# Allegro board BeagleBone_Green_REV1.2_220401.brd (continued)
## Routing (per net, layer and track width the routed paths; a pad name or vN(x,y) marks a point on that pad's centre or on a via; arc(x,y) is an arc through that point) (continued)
UART0_RX: length 28.4
  TOP w0.121: v1(40.92,25.21) U5.E15
  LYR4 w0.133: v1(43.61,11.33) 41.4,13.54 41.4,14.66 40.69,15.37 40.69,20.47 39.45,21.71 39.45,24.28 39.96,24.79 40.5,24.79 v1(40.92,25.21)
  BOTTOM w0.121: U15.6 53.22,11.68 52.33,12.57 50.16,12.57 49.31,11.72 44.01,11.72 v1(43.61,11.33)
UART0_TX: length 28.7
  TOP w0.121: v1(40.12,25.21) U5.E16
  LYR4 w0.133: v1(40.12,25.21) 40.01,25.21 39.19,24.39 39.19,21.59 40.41,20.37 40.41,15.01 41.17,14.26 41.17,13.14 v1(43.03,11.28)
  BOTTOM w0.121: U15.5 53.23,12.18 52.59,12.81 49.9,12.81 49.12,12.04 43.41,12.04 43.03,11.66 v1(43.03,11.28)
UART1_RXD: length 25.6
  TOP w0.121: v1(40.13,24.38) 40.13,24.42 U5.D16
  LYR4 w0.121: v1(40.13,24.38) 40.52,24 40.52,21.84 40.72,21.64
  LYR4 w0.133: 40.72,21.64 41.5,20.85 41.5,15.62 42.21,14.91 42.21,14.04 44.58,11.68 44.58,9.4 v1(45.09,8.89)
  BOTTOM w0.121: P9.26 48.77,5.84 47.75,5.84 46.35,7.24 46.35,8.13 45.59,8.89 v1(45.09,8.89)
UART1_TXD: length 23.3
  TOP w0.121: v1(40.92,24.41) U5.D15
  LYR4 w0.121: 41.32,23.37 41.32,24.01 v1(40.92,24.41)
  LYR4 w0.133: P9.24 46.13,5.94 46.13,8.74 44.88,9.98 44.88,11.71 42.52,14.07 42.52,15.01 41.74,15.79 41.74,21 41.33,21.41 41.33,23.35 41.32,23.37
UART2_RXD: length 83.2
  TOP w0.121: J5.1 v1(78.23,36.4) ; U5.A17 39.72,22.19 38.09,20.57 38.09,12.99 40.74,10.34 v1(40.74,10.21) 40.84,10.11 40.84,6.78 41.66,5.97 43.56,5.97 P9.22
  LYR3 w0.133: v1(40.74,10.21) 41.01,10.48 46.16,10.48 46.93,9.71 54.79,9.71 54.94,9.85 54.94,10.36 55.37,10.79 56.9,10.79 57.94,11.84 69.24,11.84 78.69,21.28 78.69,35.94 v1(78.23,36.4)
UART2_TXD: length 84.2
  TOP w0.121: U5.B17 39.32,22.81 39.32,22.17 37.85,20.7 37.85,12.45 v1(40.03,10.26) 40.51,9.78 40.51,6.6 41.53,5.59 43.05,5.59 43.81,4.83 43.81,3.17 P9.21 ; J5.2 v1(78.23,34.4)
  LYR3 w0.133: v1(78.23,34.4) 78.23,21.46 68.97,12.2 55.89,12.2 53.63,9.94 47.08,9.94 46.3,10.72 40.49,10.72 v1(40.03,10.26)
UART4_RXD: length 41.6
  TOP w0.121: v1(37.08,36.7) 37.21,36.58 37.21,36.35 37.52,36.04 37.52,36 38.7,34.81 39.32,34.81 U5.T17
  LYR4 w0.133: v1(33.15,6.48) 33.15,16.38 34.29,17.53 34.29,21.69 34.51,21.9 34.51,21.93 34.54,21.97 34.54,35.31 35.37,36.13 36.46,36.13 37.03,36.7 v1(37.08,36.7)
  BOTTOM w0.121: P9.11 33.66,3.17 33.66,5.4 33.15,5.91 v1(33.15,6.48)
UART4_TXD: length 44.6
  TOP w0.121: U5.U17 39.32,35.61 38.68,35.61 38.35,35.94 38.35,36.06 38.2,36.21 v1(38.2,36.22) ; P9.13 33.66,3.17 33.66,5.08 v1(32.26,6.48)
  LYR4 w0.121: 38.19,36.22 v1(38.2,36.22)
  LYR4 w0.133: 38.19,36.22 37.92,36.22 37.49,36.65 37.49,37.69 37.08,38.1 35.81,38.1 34.04,36.32 34.04,22.1 33.78,21.84 33.78,18.03 32.26,16.51 v1(32.26,6.48)
USB0_DM: length 42.5
  TOP w0.114: v1(10.79,43.26) 10.79,43.27 10.79,43.56 10.92,43.69 11.34,43.69 11.66,43.37 11.66,42.49 12.24,41.91 U10.2 12.8,41.91 13.02,42.13 13.02,42.69 13.13,42.8 15.49,42.8 16.48,41.81 16.48,41.29 17.38,40.39 22.21,40.39 25.74,36.86 29.42,36.86 30.08,36.2 33.87,36.2 34.52,35.55 34.52,35.28 34.69,35.11 34.96,35.11 35.18,34.89 35.18,34.67 35.36,34.49 35.57,34.49 36.07,34 36.07,32.94 36.78,32.23 37.03,32.23 37.18,32.38 37.45,32.38 37.59,32.23 37.92,32.23 38.07,32.38 38.4,32.38 38.65,32.13 38.8,32.13 U5.N18
  BOTTOM w0.114: P4.2 10.58,43.48 v1(10.79,43.26)
USB0_DP: length 42.5
  TOP w0.114: v1(10.79,44.07) 10.9,43.97 11.46,43.97 11.94,43.49 11.94,42.61 12.14,42.41 U10.1 12.7,42.53 12.7,42.88 12.9,43.08 15.61,43.08 16.76,41.92 16.76,41.4 17.5,40.67 22.33,40.67 25.86,37.13 29.54,37.13 30.2,36.47 33.99,36.47 36.35,34.11 36.35,33.06 36.75,32.66 38.51,32.66 38.76,32.41 39.32,32.41 U5.N17
  BOTTOM w0.114: v1(10.79,44.07) 10.79,44.02 10.54,43.76 5.9,43.76 5.52,44.13 P4.3
USB0_ID: length 48.4
  TOP w0.121: U5.P16 v1(40.12,33.21) ; U10.3 12.58,41.02 12.71,40.89 14.61,40.89 v1(15.62,41.91)
  LYR3 w0.133: v1(15.62,41.91) 16.01,41.91 16.09,41.83 26.47,41.83 27.05,41.25 31.19,41.25 31.21,41.22 31.88,41.22 32.52,40.58 34.73,40.58 35.61,39.7 36.5,39.7 37.49,38.71 37.49,36.3 38.52,35.26 40.25,35.26 40.49,35.03 40.49,33.58 v1(40.12,33.21)
  BOTTOM w0.121: v1(15.62,41.91) 15.54,41.99 15.54,42.98 13.56,44.96 5.85,44.96 5.68,44.78 P4.4
USB1_DM: length 61.1
  TOP w0.114: v1(36.22,34.98) 36.14,34.9 36.14,34.74 36.33,34.54 37.17,34.54 37.98,33.73 38.8,33.73 U5.R18
  LYR3 w0.127: v1(15.06,16.36) 15.06,16.28 14.78,16 14.42,16 14,16.43 14,18.19 16.99,21.18 18.26,21.18 21.26,24.18 21.26,27.1 22.23,28.07 22.23,34.29 21.84,34.67 20.62,34.67 19.68,35.61 19.68,38.56 19.99,38.86 22.61,38.86 23.62,37.85 33.91,37.85 35.97,35.79 35.97,35.38 36.22,35.13 v1(36.22,34.98)
  BOTTOM w0.114: P3.2 10.28,12.17 10.92,11.53 12.2,11.53 13.94,13.26 13.94,13.54 13.72,13.76 U9.2 13.72,14.45 13.87,14.61 14.51,14.61 14.68,14.77 14.68,16.08 14.96,16.36 v1(15.06,16.36)
USB1_DP: length 61.1
  TOP w0.114: U5.R17 39.64,33.61 39.24,34.01 38.1,34.01 37.13,34.98 v1(36.86,34.98)
  LYR3 w0.127: v1(36.86,34.98) 36.73,35.1 36.68,35.1 36.53,35.25 36.27,35.51 36.27,35.92 34.04,38.15 23.75,38.15 22.73,39.17 19.86,39.17 19.38,38.68 19.38,35.48 20.5,34.37 21.72,34.37 21.92,34.16 21.92,28.19 20.95,27.23 20.95,24.31 18.14,21.49 16.87,21.49 13.69,18.31 13.69,16.3 14.24,15.75 v1(15.14,15.75)
  BOTTOM w0.114: P3.3 10.72,11.25 12.32,11.25 14.22,13.15 U9.1 14.22,14.24 14.3,14.33 14.63,14.33 14.96,14.66 14.96,15.57 v1(15.14,15.75)
USB1_DRVVBUS: length 60.9
  TOP w0.121: U5.F15 v1(40.92,26.01)
  LYR3 w0.133: v1(3.62,7.59) 3.62,8.33 4.58,9.3 21.69,9.3 22.23,8.76 28.88,8.76 29.48,8.17 36.24,8.17 36.29,8.22 39.66,8.22 v1(39.85,8.41)
  LYR4 w0.121: 38.93,24.76 40.18,26.01 v1(40.92,26.01)
  LYR4 w0.133: 38.93,24.76 38.93,21.32 39.52,20.73 39.52,19.41 40.13,18.8 40.13,14.71 40.59,14.25 40.59,12.4 39.5,11.3 39.5,8.76 v1(39.85,8.41)
  BOTTOM w0.121: R53.1 3.63,6.94 3.62,6.95 v1(3.62,7.59) 3.65,7.62 U8.4
USB1_ID: length 1.9
  TOP w0.121: U5.P17 39.37,33.16 v1(39.32,33.21)
  BOTTOM w0.121: v1(39.32,33.21) 39.32,33.71 39.05,33.97 R49.2
USB1_OCN: length 65.3
  TOP w0.121: U5.T16 40.11,34.82 40.11,34.83 v1(40.08,34.86)
  LYR3 w0.121: 38.1,35.31 37.34,36.07 36.83,36.07 36.58,36.32 36.58,37.85
  LYR3 w0.133: v1(12.93,38.93) 14.9,40.89 23.75,40.89 25.53,39.12 34.19,39.12 35.2,38.1 36.32,38.1 36.58,37.85 ; 38.1,35.31 38.48,34.92 39.64,34.92 39.71,34.86 v1(40.08,34.86)
  LYR4 w0.133: v1(3.12,15.27) 3.4,15.54 7.84,15.54 13.26,20.95 13.26,38.6 v1(12.93,38.93)
  BOTTOM w0.121: R52.2 3.1,15.24 v1(3.12,15.27) 3.65,14.74 U8.5
USB1_PWR: length 9.8
  LYR3 w0.381: v1(5.97,14.61) 7.49,14.61 9.4,16.51 v1(12.7,16.51)
  BOTTOM w0.254: U9.6 14.22,15.38 13.08,16.51 v1(12.7,16.51)
USB1_VBUS: length 55.8
  TOP w0.305: v1(36.08,37.59) 36.41,37.26 36.41,37.25 36.58,37.08 36.58,36.5 37.18,35.9 37.18,35.83 38.59,34.41 U5.T18
  LYR3 w0.381: v1(20.95,39.75) 20.95,39.9 21.34,40.28 22.33,40.28 23.88,38.73 33.96,38.73 35.1,37.59 v1(36.08,37.59)
  LYR4 w0.381: v1(20.32,25.02) 19.92,25.42 19.92,38.71 v1(20.95,39.75)
  BOTTOM w0.381: R36.1 8.35,16 9.16,16.81 9.19,16.81 9.4,17.02 12.09,17.02 16.54,21.46 17.65,21.46 20.32,24.13 v1(20.32,25.02)
USB_DC: length 26.6
  TOP w0.254: U10.6 14.38,42.41 14.66,42.14 v1(14.73,42.14)
  LYR3 w0.381: v1(36.86,38.51) 36.86,38.66 36.25,39.27 35.31,39.27 34.49,40.08 32.31,40.08 31.62,40.77 29.08,40.77 28.62,40.3 27.19,40.3 26.11,41.38 15.11,41.38 14.73,41.76 v1(14.73,42.14)
  BOTTOM w0.381: 37.72,38.48 36.88,38.48 v1(36.86,38.51)
  vias: v1(19.3,11.4) v1(19.25,10.82) v1(19.81,11.05) v2(11.18,42.16) v2(11.2,41.15) v2(11.94,41.12)
USR0: length 26.3
  TOP w0.121: U5.V15 41.32,36.99 40.6,37.71 40.07,37.71 39.53,38.25 37.7,38.25 36.96,38.99 35.87,38.99 35.85,39.01 35.52,39.01 35.5,38.99 34.9,38.99 33.88,37.97 26.31,37.97 24.64,39.65 24.64,40.03 22.63,42.04 R76.1 21.46,42.55 20.32,42.55 19.94,42.93 Q1.2
USR1: length 30.9
  TOP w0.121: Q1.5 19.94,45.72 20.19,45.97 21.46,45.97 R77.1 22.73,44.7 22.73,42.34 24.92,40.16 24.92,39.75 26.44,38.23 33.71,38.23 34.72,39.24 35.41,39.24 35.42,39.26 35.96,39.26 35.97,39.24 37.06,39.24 37.81,38.49 39.63,38.49 40.17,37.95 40.75,37.95 41.72,36.99 41.72,35.61 U5.U15
USR2: length 30.7
  TOP w0.121: Q2.2 v1(17.27,42.51) 17.27,42.1 17.72,41.66 R78.1 ; v1(40.91,34.82) 40.91,34.82 U5.T15
  LYR3 w0.133: v1(40.91,34.82) 40.91,34.98 40.36,35.52 38.9,35.52 38.73,35.69 38.73,36.32 38.48,36.58 38.48,36.96 37.81,37.63 37.81,38.83 36.56,40.08 35.61,40.08 34.8,40.89 32.7,40.89 32.13,41.46 31.31,41.46 31.29,41.48 29.81,41.48 29.24,42.06 28.24,42.06 28.24,42.07 27.9,42.07 27.9,42.06 17.72,42.06 v1(17.27,42.51)
USR3: length 29.8
  TOP w0.121: U5.V16 40.52,37.2 40.27,37.46 39.91,37.46 39.37,38 34.29,38 34.01,37.72 26.15,37.72 24.16,39.71 24.16,40.13 22.81,41.48 21.64,41.48 21.5,41.63 21.5,42 21.33,42.16 20.45,42.16 R79.1 19.94,42.29 19.68,42.55 19.08,42.55 18.39,43.23 18.39,43.87 18.19,44.07 17.4,44.07 17.27,44.2 Q2.5
VDCDC1:
  vias: v1(20.07,9.91) v1(20.7,9.91)
VIO: length 22
  TOP w0.121: v1(22.2,11.2) 22.66,11.66 U2.18 ; v1(30.25,9.25) 30.68,8.81 31.71,8.81 32.4,8.12 U16.5
  LYR3 w0.133: v1(22.2,11.2) 22.96,11.2 23.75,10.41 28.88,10.41 30.05,9.25 v1(30.25,9.25)
  BOTTOM w0.121: v1(22.2,11.2) C146.1 21.76,12.01 20.01,13.77 18.11,13.77 16.38,15.49 R7.2
VLDO1: length 4.5
  TOP w0.203: 19.05,16.64 U2.3
  TOP w0.254: v1(18.29,16.76) 18.41,16.64 19.05,16.64
  BOTTOM w0.381: v1(18.29,16.76) 17.65,16.13 17.4,16.13 17.4,17.91
VREFP_ADC: length 7.7
  TOP w0.121: 45.59,21.72 45.72,21.84 45.72,22.81
  TOP w0.254: 45.72,22.81 U5.B9
  TOP w0.305: 45.29,21.42 45.59,21.72
  TOP w0.381: C32.1 C31.1 C33.1 44.1,18.32 R27.2 44.1,19.54 45.21,20.65 45.21,21.34 45.29,21.42
VRTC: length 41.9
  TOP w0.254: v1(48.12,24.41) U5.D7
  LYR3 w0.381: v1(16.89,20.32) 20.57,20.32 20.95,20.7 25.53,20.7 26.67,21.84 33.78,21.84 35.18,20.45 37.44,20.45 37.44,20.45 37.59,20.45 38.38,19.66 46.08,19.66 47.31,20.89 v1(47.31,20.95)
  BOTTOM w0.178: v1(49.21,20.95) 49.4,20.95 49.69,20.67 49.69,19.3 49.82,19.18 R26.1
  BOTTOM w0.381: R5.2 C16.1 15.11,18.97 16.46,20.32 v1(16.89,20.32) ; C105.1 v1(47.31,20.95)
WAKEUP: length 63.4
  TOP w0.121: U2.13 20.66,11.6 21.08,11.18 v1(21.08,11.17) ; U5.C5 v1(49.72,23.61)
  LYR3 w0.133: v1(58.42,11.43) 55.88,8.89 46.48,8.89 45.72,9.65 41.71,9.65 41.35,9.3 34.44,9.3 33.83,8.69 29.84,8.69 29.13,9.4 24.13,9.4 22.86,10.67 21.58,10.67 v1(21.08,11.17)
  LYR4 w0.133: v1(58.42,11.43) 58.42,16.51 54.99,19.94 54.74,19.94 53.47,21.21 50.61,21.21 49.28,22.55 49.28,23.16 v1(49.72,23.61)
  BOTTOM w0.121: v1(49.72,23.61) 50.12,23.21 50.12,22.54 50.16,22.5 R26.2
WP: length 9.1
  BOTTOM w0.121: U7.5 28.09,22.86 27.43,23.51 25.68,23.51 25.08,22.92 R156.2 24.64,22.42 24.07,22.99 21.84,22.99 TP4.1
XDMA_EVENT_INTR0: length 10.7
  BOTTOM w0.121: R18.2 40.64,13.84 40.39,14.1 39.57,14.1 39.38,14.29 36,14.29 34.92,15.37 34.92,16.76 34.23,17.46 P2.17
YEL_C: length 5.5
  BOTTOM w0.381: R130.2 5.14,30.71 4.29,29.86 4.29,27 P5.11
YELA: length 29.5
  TOP w0.254: U14.2 v1(23.83,27.43)
  BOTTOM w0.254: v1(23.83,27.43) 23.32,26.92 21.21,26.92 17.91,23.62 14.66,23.62 11.73,26.54 10.67,26.54 9.14,28.07 5.46,28.07 5.21,27.81
  BOTTOM w0.381: P5.12 4.88,26.37 5.21,26.7 R135.1
ZQ: length 2.5
  TOP w0.121: v1(66.3,22.36) U12.L8
  BOTTOM w0.121: v1(66.3,22.36) 66.7,21.96 R99.2
N21757673: length 4.3
  BOTTOM w0.121: U4.4 16.89,40.26 16.13,39.5 R10.1 C19.1 R11.2
N21769115: length 5.9
  TOP w0.121: S2.3 S2.1 77.34,45.11 77.34,45.85 76.83,46.35 R75.2
N22155575: length 7.4
  TOP w0.121: v1(40.92,33.21) U5.P15
  LYR3 w0.133: v1(40.92,35.59) 40.92,35.53 41.31,35.14 41.31,33.6 v1(40.92,33.21)
  BOTTOM w0.381: R159.2 39.37,38.48 40.51,37.34 40.51,35.99 v1(40.92,35.59)
N22248684: length 1.5
  TOP w0.121: R167.1 38.48,42.8 39.18,42.1 Y4.3
N22287501: length 16
  TOP w0.121: U3.4 40.99,47.23 40.97,47.24 40.97,47.55 40.64,47.88 37.34,47.88 36.32,48.9 28.24,48.9 v1(27.51,48.16)
  BOTTOM w0.121: R162.1 v1(27.51,48.16)
N22287555: length 18.5
  TOP w0.121: U3.2 40.34,44.07 39.95,43.69 37.41,43.69 36.27,42.55 36.27,40.38 37.9,38.75 40.07,38.75 v1(40.34,39.01) ; v1(41.72,34.01) U5.R14
  LYR3 w0.121: v1(41.72,34.01) 42.12,34.41 42.12,35.1
  LYR3 w0.133: v1(40.34,39.01) 40.84,38.51 40.84,36.37 42.12,35.1
N22420400: length 13.2
  TOP w0.203: U2.4 18.91,16.24 18.8,16.13 19.09,15.84 U2.5
  TOP w0.381: TP5.1 15.16,10.67 16.42,11.92 16.42,14.99 17.55,16.13 18.8,16.13
  BOTTOM w0.381: R173.1 R174.2 14.05,9.98 TP5.1
N22420444: length 12.8
  TOP w0.203: TP6.1 16.1,9.5 16.1,10.97 16.89,11.76 16.89,14.76 17.57,15.44 U2.6
  BOTTOM w0.203: TP6.1 13.89,8.97 R174.1
N22420447: length 4.1
  TOP w0.203: TP7.1 17.27,10.82 18.59,12.14 18.59,12.75 19.28,13.44 U2.11
N22488252: length 24.3
  TOP w0.121: TP9.1 24.91,23.51 28.43,23.51 30.99,20.95 30.99,20.04 32.36,18.66 33.39,18.66 34.28,19.56 34.28,22.09 35.56,23.37 35.56,24 35.96,24.4 37.36,24.4 38.17,25.21 39.32,25.21 U5.E17
N22569088: length 3.6
  TOP w0.762: v1(76.45,27.91) J5.4
  BOTTOM w0.762: R147.2 76.38,27.94 76.4,27.91 v1(76.45,27.91)
N22569092: length 4.5
  TOP w0.762: J4.4 v1(74.5,15.54)
  BOTTOM w0.762: v1(74.5,15.54) 73.68,15.54 72.52,16.7 R146.2
N22710186: length 6.8
  TOP w0.121: U5.U9 46.52,35.61 46.52,41.39 R32.1
N22710189: length 17.2
  TOP w0.121: v1(44.69,45.52) 45.22,44.99 45.22,44.52 45.14,44.44 44.27,44.44 44.15,44.32 44.15,44.08 44.27,43.96 45.14,43.96 45.26,43.84 45.26,43.6 45.14,43.48 44.27,43.48 44.15,43.36 44.15,43.11 44.27,42.99 45.14,42.99 45.26,42.87 45.26,42.63 45.14,42.51 44.27,42.51 44.15,42.39 44.15,41.4 46.24,39.31 46.24,36.47 46.12,36.35 U5.V9
  BOTTOM w0.121: R33.1 43.41,46.44 44.07,45.79 44.42,45.79 v1(44.69,45.52)
N22740401: length 10.8
  BOTTOM w0.121: R148.2 34.67,39.89 34.76,39.98 U6.4 34.17,40.37 33.91,40.64 C145.1 33.4,39.75 31.88,38.23 31.88,36.83 31.73,36.68 30.75,36.68 30.63,36.81 30.63,38.05 30.29,38.39 U1.2
N22823317: length 3.8
  TOP w0.121: U2.33 26.36,16.24 27.05,16.94 27.05,17.37 27.55,17.88 28.1,17.88 28.57,18.35 R175.1
N22823323: length 2.8
  TOP w0.121: U2.34 25.94,16.65 26.41,16.65 26.8,17.03 26.8,17.47 27.69,18.36 R176.1
N22872429: length 6.2
  BOTTOM w0.121: Y2.3 44.5,44.05 44.09,43.65 C26.1 43.65,43.59 43.56,43.49 43.56,41.05 43.81,40.79 44.83,40.79

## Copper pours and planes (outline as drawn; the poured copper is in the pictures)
DGND on TOP (solid shape): 6.53,9.17 2.72,9.17 2.72,12.98 6.53,12.98
DGND on TOP: 41.66,43.69 41.91,43.43 41.91,39.62 41.66,39.37 40.01,39.37 39.62,38.99 37.97,38.99 36.7,40.26 36.7,42.67 37.72,43.69
DGND on TOP: 13.72,20.7 18.41,20.7 18.54,20.57 18.54,19.18 17.91,18.54 16.76,18.54 16.26,18.03 16.26,16.26 16,16 13.84,16 13.46,15.62 12.19,15.62 12.06,15.75 12.06,19.05
DGND on TOP: 24.05,9.19 27.1,9.19 27.2,9.09 27.2,6.93 27.03,6.76 25.53,6.76 24.97,7.32 24.28,7.32 23.9,7.7 23.9,9.04
DGND on TOP: 30.73,19.68 32.26,18.16 32.26,15.77 32,15.52 28.47,15.52 28.3,15.7 28.3,16.64 28.4,16.74 29.39,16.74 29.67,17.02 29.67,18.11 28.88,18.9 27.51,18.9 27.33,19.08 27.33,21.36 27.69,21.72 29.72,21.72 30.73,20.7
DGND on TOP: 58.39,35.38 67.36,35.38 70.59,32.16 70.59,15.75 69.75,14.91 62.38,14.91 58.27,10.79 49.17,10.79 48.54,11.43 48.54,13 49.1,13.56 56.21,13.56 56.34,13.69 56.87,13.69 58.85,15.67 58.85,15.98 59.13,16.26 66.78,16.26 68,17.48 68,31.09 64.63,34.46 58.46,34.46 58.19,34.72 58.19,35.18
DGND on BOTTOM: 19.56,16.07 19.56,15.75 19.89,15.42 20.65,15.42 20.95,15.11 20.95,13.39 21.08,13.26 21.08,13.21 22.54,13.21 23.11,13.78 24.13,13.78 24.38,14.03 24.38,14.67 25.15,14.67 25.15,14.41 25.4,14.16 26.04,14.16 26.29,14.41 26.29,16.59 26.09,16.79 25.3,16.79 25.15,16.64 25.15,15.81 24.38,15.81 24.38,16.56 24.18,16.76 23.47,16.76 23.24,16.54 23.24,15.81 22.48,15.81 22.48,16.54 22.28,16.74 21.46,16.74 21.34,16.61 20.42,16.61 20.37,16.66 19.63,16.66 19.56,16.59 19.56,16.43 19.56,16.43 19.56,16.07
DGND on BOTTOM: 25.9,32.75 26.52,32.13 26.52,28.4 26.37,28.24 23.77,28.24 23.65,28.37 23.65,32.41 23.99,32.75
DGND on BOTTOM: 32.77,29.24 33.07,29.24 33.35,29.51 33.35,30.07 33.43,30.15 34.04,30.15 34.11,30.07 34.11,24.03 33.78,23.7 33.02,23.7 32.64,24.08 32.64,26.37 32.74,26.47 32.74,29.21
DGND on BOTTOM: 8.03,45.24 3.99,45.24 3.94,45.29 3.94,45.75 5.31,45.75 5.69,46.13 5.69,52.3 5.89,52.5 7.75,52.5 8.36,51.89 8.36,45.57
DGND on BOTTOM: 51.89,36.6 52.25,36.96 66.73,36.96 70.05,33.63 70.05,32.36 69.49,31.8 69.49,29.31 71.6,27.2 71.6,13.64 71.02,13.06 62.23,13.06 60.2,15.09 56.87,15.09 55.6,16.36 52.53,16.36 51.77,17.12 51.77,19.46 52.37,19.46 52.7,19.13 54.15,19.13 57.23,16.05 67.74,16.05 68.25,16.56 68.25,17.73 68.15,17.83 68.15,18.21 68.63,18.69 68.63,25.78 68.61,25.81 69.11,26.31 69.29,26.31 69.29,27.79 68.66,28.42 68.66,31.6 67.87,32.38 65.86,32.38 63.96,34.29 53.01,34.29 51.89,35.41 ; 2 cut-outs
DGND on BOTTOM: 41.27,30.48 41.4,30.61 41.4,30.99 41.91,30.99 41.91,30.61 42.16,30.35 42.16,29.72 41.91,29.46 41.91,29.08 41.27,29.08
DGND on LYR2_GND: 16.51,6.03 18.77,3.77 18.77,2.69 19.1,2.36 74.74,2.36 77.15,4.78 77.15,8.26 83.45,14.55 83.46,14.55 83.77,14.86 83.77,40.53 79.53,44.76 79.53,44.81 77.16,47.19 77.15,47.19 75.13,49.2 75.13,51.49 74.35,52.27 18.81,52.27 18.1,51.56 18.1,50.16 16.51,48.58 12.7,48.58 11.11,50.16 11.11,52.39 10.79,52.7 6.35,52.7 5.8,52.67 5.25,52.57 5.26,52.56 5.26,49 5.23,49 4.04,47.8 4.04,43.08 4.39,42.72 5.79,42.72 8.86,39.65 12.65,39.65 13.26,39.04 13.26,35.84 11.71,34.29 4.39,34.29 3.73,33.63 3.73,27.43 5.08,26.09 11.3,26.09 13.06,24.33 13.06,20.6 8.64,16.18 6.22,16.18 3.45,18.95 2.77,18.95 2.59,18.77 2.59,6.68 3.15,6.12 4.93,6.12 5.94,7.14 9.3,7.14 10.4,6.03
DGND on LYR3: 58.67,35.86 61.93,35.86 65.41,32.38 69.65,32.38 70.54,31.5 70.54,19.38 66.6,15.44 55.58,15.44 54.99,16.03 54.99,16.87 55.12,16.99 55.6,16.99 56.21,16.38 56.21,16.28 56.57,15.93 62.66,15.93 63.14,16.41 65.25,16.41 66.55,17.7 66.55,30.23 61.98,34.8 58.67,34.8 58.42,35.05 58.42,35.61
DGND on LYR3: 40.13,39.24 40.01,39.12 40.01,38.1 40.51,37.59 40.51,36.07 40.26,35.81 39.12,35.81 38.99,35.94 38.99,36.45 38.73,36.7 38.73,37.08 38.1,37.72 38.1,38.99 37.72,39.37 37.72,40.77 37.97,41.02 40.89,41.02 41.02,40.89 41.02,39.37 40.89,39.24
DGND on LYR5_PWR: 39.62,4.57 60.58,4.57 61.21,5.21 61.21,15.6 61.39,15.77 67.03,15.77 69.37,18.11 69.39,18.11 69.39,29.87 64.72,34.54 63.47,34.54 62.64,35.38 62.64,40.87 64.77,43 75.18,43 76.28,44.09 76.28,46.76 76.58,47.07 77.27,47.07 83.9,40.44 83.9,13.64 77.04,6.78 77.04,3.81 74.7,1.47 26.72,1.47 26.16,2.03 26.16,5.08 26.29,5.21 38.99,5.21
GND_EARTH on TOP: outline of 106 points within 0.28,0.33 86,54.25
GND_EARTH on BOTTOM: outline of 107 points within 0.28,0.33 86,54.25
GND_EARTH on LYR2_GND: outline of 107 points within 0.28,0.33 86,54.25
GND_EARTH on LYR3: outline of 106 points within 0.28,0.33 86,54.25
GND_EARTH on LYR4: outline of 107 points within 0.28,0.33 86,54.25
GND_EARTH on LYR5_PWR: outline of 106 points within 0.28,0.33 86,54.25
GND_OSC1 on TOP: 48.26,14.38 48.64,14 53.42,14 53.98,14.55 53.98,17.78 53.09,18.67 52.32,18.67 51.05,19.94 51.05,21.84 50.16,22.73 48.9,22.73 48.77,22.61 48.77,20.19 48.13,19.56 48.13,18.67 48.26,18.54
VBUS on BOTTOM: 10.67,14.22 11.18,14.73 11.18,16 10.85,16.33 9.22,16.33 8.51,15.62 6.71,15.62 6.68,15.6 6.68,14.25 6.71,14.22
VDD_1V8 on LYR3: 40.28,32.26 33.02,32.26 32.77,32.51 32.77,34.29 33.02,34.54 40.01,34.54 40.41,34.14 40.41,32.38
VDD_1V8 on LYR4: 45.72,25.15 45.47,24.89 41.66,24.89 41.4,25.15 41.4,28.45 41.15,28.7 40.01,28.7 39.75,28.96 39.75,34.29 40.01,34.54 42.55,34.54 42.8,34.8 42.8,35.26 43.18,35.64 45.14,35.64 45.72,35.05 45.72,29.72 45.34,29.34 45.34,29.08 45.72,28.7
VDD_1V8 on LYR5_PWR: 32.51,34.29 32.26,34.04 32.26,28.19 29.59,25.53 29.59,25.27 27.69,23.37 27.69,21.84 26.42,20.57 26.42,17.53 26.67,17.27 30.73,17.27 30.99,17.53 30.99,20.57 33.78,23.37 33.78,34.04 33.53,34.29
VDD_1V8 on LYR5_PWR: 44.7,13.97 44.7,25.27 44.83,25.4 46.74,25.4 46.86,25.27 46.86,20.45 47.24,20.07 48.9,20.07 49.15,19.81 49.15,13.97 48.9,13.72 44.96,13.72
VDD_3V3A on BOTTOM: 39.88,29.72 40.39,29.72 40.77,29.34 40.77,29.08 41.02,28.83 41.66,28.83 41.91,28.57 41.91,27.56 41.4,27.56 41.4,27.94 41.02,28.32 40.51,28.32 40.26,28.57 38.61,28.57 38.61,29.08 39.24,29.08
VDD_3V3A on BOTTOM: 48.13,33.02 50.04,33.02 50.29,33.27 50.29,35.18 50.76,35.64 50.76,36.45 50.29,36.45 50.29,35.81 49.91,35.43 49.91,33.91 49.53,33.91 49.53,35.43 49.15,35.81 49.15,36.45 48.69,36.45 48.69,35.86 48.26,35.43 48.26,33.66 48.01,33.4 48.01,33.15
VDD_3V3A on BOTTOM: 42.29,36.45 42.29,35.81 41.91,35.43 41.91,33.27 42.16,33.02 43.31,33.02 43.43,33.15 43.43,33.27 43.05,33.66 43.05,35.56 42.76,35.85 42.76,36.45
VDD_3V3A on LYR5_PWR: 21.59,11.68 21.34,11.94 21.34,23.37 21.59,23.62 27.18,23.62 27.43,23.37 27.43,22.1 26.16,20.83 26.16,17.4 26.54,17.02 30.86,17.02 31.24,17.4 31.24,20.45 34.04,23.24 34.04,34.04 33.27,34.8 32.51,34.8 32.26,35.05 32.26,37.08 37.85,42.67 37.85,43.74 38.48,44.37 39.4,44.37 40.06,43.71 49.73,43.71 53.39,47.37 75.31,47.37 76,46.69 76,44.55 75.08,43.64 64.47,43.64 62.03,41.2 62.03,35.38 61.19,34.54 50.55,34.54 50.16,34.16 50.16,31.5 49.15,30.48 49.15,29.46 48.9,29.21 42.55,29.21 42.04,28.7 42.04,28.32 41.91,28.19 40.64,28.19 40.39,27.94 40.39,27.3 40.64,27.05 41.91,27.05 42.16,26.8 42.16,26.54 41.15,25.53 41.15,24.89 41.4,24.64 42.8,24.64 43.05,24.89 43.05,25.27 43.18,25.4 44.32,25.4 44.45,25.27 44.45,13.84 44.83,13.46 48.9,13.46 49.15,13.21 49.15,5.59 48.9,5.33 39.88,5.33 39.62,5.59 39.62,11.3 39.24,11.68
VDD_3V3B on BOTTOM: 26.35,33.97 26.35,33.53 26.29,33.53 26.29,33.27 26.16,33.15 24.13,33.15 24,33.27 24,34.67 22.99,35.69 22.1,35.69 21.97,35.81 21.97,37.59 22.23,37.85 24.26,37.85 24.51,37.59 25.02,37.59 25.27,37.34 25.27,36.7 25.4,36.58 25.4,34.29 25.53,34.16 26.16,34.16
VDD_3V3B on BOTTOM: 71.37,36.96 69.85,36.96 69.6,37.21 69.6,37.85 68.45,38.99 67.44,38.99 67.18,39.24 67.18,39.5 67.06,39.62 66.17,39.62 66.04,39.5 66.04,39.12 66.17,38.99 66.67,38.99 67.06,38.61 67.06,37.34 67.69,36.7 67.69,36.45 67.82,36.32 69.85,36.32 69.98,36.45 71.37,36.45 71.5,36.58 71.5,36.83
VDD_3V3B on LYR5_PWR: 16.51,6.03 12.7,6.03 12.69,6.03 11.23,7.49 2.74,7.49 2.48,7.76 2.51,7.8 2.51,15.93 3.05,16.46 8.2,16.46 12.7,20.95 12.7,22.99 12.95,23.24 17.78,23.24 21.46,26.92 23.24,26.92 23.62,27.3 23.62,36.96 23.24,37.34 14.1,37.34 12.06,39.37 8.97,39.37 3.86,44.48 3.86,47.68 5.69,49.35 5.69,52.66 6.02,52.69 6.35,52.7 10.79,52.7 11.11,52.39 11.11,50.16 12.7,48.58 16.51,48.58 18.1,50.16 18.1,51.79 18.57,52.26 18.57,52.27 75.62,52.27 76.48,51.41 76.48,48.06 76.05,47.62 52.65,47.62 49.15,44.12 40.16,44.12 39.62,44.65 38.38,44.65 37.59,43.87 37.59,42.8 32,37.21 32,28.45 27.43,23.88 21.46,23.88 21.08,23.5 21.08,11.81 21.46,11.43 39.05,11.43 39.37,11.11 39.37,5.71 39.05,5.4 26.04,5.4 25.72,5.08 25.72,3.15 25.23,2.67 19.88,2.67
VDD_5V on TOP: 19.26,13.74 19.26,13.94 17.8,13.94 17.25,13.39 17.25,12.29 17.4,12.14 18.26,12.14 18.36,12.24 18.36,12.99 19.11,13.74
VDD_5V on BOTTOM: 16.66,13.64 18.57,13.64 19,13.21 19,12.14 18.41,11.56 16.76,11.56 16.51,11.81 16.51,12.29 16.54,12.32 16.54,13.51
VDD_5V on LYR4: 18.31,13.34 18.69,12.95 18.69,8.81 19.29,8.22 21.5,8.22 23.04,6.68 24.56,6.68 26.31,4.93 26.31,3.63 25.81,3.12 19.13,3.12 15.6,6.65 15.57,6.65 15.57,12.75 16.15,13.34
VDD_CORE on TOP: 27.3,14.1 27.3,12.95 27.56,12.7 30.63,12.7 31.5,13.56 31.5,14.73 31.38,14.85 26.6,14.85 26.49,14.74 25.91,14.74 25.91,14.54 26.86,14.54
VDD_CORE on BOTTOM: 34.52,30.12 34.98,30.12 35.89,29.21 35.89,24.77 35.74,24.61 35.43,24.61 35.28,24.46 35.28,23.88 35.15,23.75 34.54,23.75 34.39,23.9 34.39,30
VDD_CORE on LYR3: 49.15,25.53 45.97,25.53 45.72,25.78 45.72,26.92 45.34,27.3 42.42,27.3 42.16,27.05 42.16,24.13 41.91,23.88 32.51,23.88 31.88,24.51 31.88,25.53 32.51,26.16 33.27,26.16 33.53,26.42 33.53,27.43 33.78,27.69 40.26,27.69 40.26,29.21 41.15,29.21 41.15,30.23 40.51,30.23 40.01,30.73 40.01,31.11 40.39,31.5 41.4,31.5 41.78,31.88 43.43,31.88 45.21,33.66 49.15,33.66 49.4,33.4 49.4,25.78
VDD_MPU on TOP: 25.21,11.75 25.02,11.75 25.02,12.38 25.72,12.38 26.54,11.56 28.83,11.56 29.46,10.92 29.46,8.13 29.08,7.75 27.94,7.75 27.69,8 27.69,9.14 27.18,9.65 26.34,9.65 25.91,10.08 25.91,11.05
VDD_MPU on TOP: 35.33,22.61 36.3,22.61 36.53,22.38 36.53,21.44 36.2,21.11 35.28,21.11 35.05,21.34 35.05,22.33
VDD_MPU on BOTTOM: 26.09,10.31 27.2,10.31 27.46,10.06 27.46,7.85 27.25,7.65 26.19,7.65 25.96,7.87 25.96,10.19
VDD_MPU on LYR3: 45.47,26.8 45.21,27.05 42.55,27.05 42.42,26.92 42.42,23.62 41.27,22.48 35.94,22.48 35.56,22.86 35.05,22.86 34.92,22.73 34.92,21.84 35.56,21.21 38.35,21.21 38.86,20.7 40.13,20.7 40.77,20.07 45.21,20.07 45.47,20.32
VDD_PHYA on BOTTOM: 22.99,33.15 22.73,32.89 22.73,31.37 22.86,31.24 23.01,31.24 23.39,30.86 23.39,27.97 23.06,27.64 22.15,27.64 21.72,28.07 21.72,32.21 21.08,32.84 21.08,34.29 21.46,34.67 23.37,34.67 23.5,34.54 23.5,33.15
VDD_PHYA on LYR5_PWR: 10.08,33.22 13.94,37.08 23.11,37.08 23.37,36.83 23.37,27.43 23.11,27.18 21.34,27.18 17.65,23.5 11.94,23.5 10.08,25.35
VDD_PLL on BOTTOM: 43.56,33.53 44.07,33.02 44.2,33.02 45.09,33.91 45.09,34.16 44.7,34.54 44.7,35.43 43.97,36.16 43.97,36.45 43.47,36.45 43.47,35.78 43.56,35.69
VDD_PLL on BOTTOM: 48.51,20.07 48.51,22.73 48.77,22.99 48.77,25.15 48.51,25.4 47.75,25.4 47.5,25.15 47.5,21.21 48.01,20.7 48.01,20.07
VDD_PLL on BOTTOM: 38.48,28.07 39.12,28.07 39.24,28.19 40.77,28.19 41.02,27.94 41.02,27.3 40.77,27.05 39.62,27.05 39.12,27.56 38.48,27.56
VDD_PLL on LYR4: 39.75,28.19 40.89,28.19 41.15,27.94 41.15,27.3 40.89,27.05 38.61,27.05 38.35,27.3 38.35,31.62 38.48,31.75 39.37,31.75 39.5,31.62 39.5,28.45
VDD_PLL on LYR5_PWR: 40.64,27.43 40.77,27.3 42.42,27.3 42.67,27.56 46.35,27.56 47.12,26.8 47.12,25.15 47.24,25.02 48.9,25.02 49.15,25.27 49.15,28.7 48.9,28.96 42.67,28.96 42.29,28.57 42.29,28.19 42.04,27.94 40.77,27.94 40.64,27.81
VDDS on BOTTOM: 38.61,22.61 39.37,22.61 39.62,22.86 39.62,23.62 39.88,23.88 41.27,23.88 41.53,24.13 41.53,24.51 41.66,24.64 41.91,24.64 42.04,24.77 42.04,25.4 41.91,25.53 41.27,25.53 40.51,26.29 39.62,26.29 39.37,26.04 39.37,25.27 39.12,25.02 38.48,25.02 38.48,22.73
VDDS on BOTTOM: 47.88,35.49 48.26,35.88 48.26,36.58 48.13,36.7 46.61,36.7 46.35,36.45 46.35,35.56 46.48,35.56 46.74,35.31 46.74,33.91 46.35,33.53 46.35,33.15 46.48,33.02 47.24,33.02 47.88,33.66
VDDS on LYR4: 46.23,25.65 45.97,25.91 45.97,28.83 45.72,29.08 45.72,29.34 45.97,29.59 45.97,34.54 46.23,34.8 49.15,34.8 49.4,34.54 49.4,24.26 49.15,24 48.01,24 47.75,24.26 47.75,25.4 47.5,25.65
VDDS on LYR5_PWR: 42.67,24.89 41.53,24.89 41.4,25.02 41.4,25.4 42.42,26.42 42.42,26.92 42.8,27.3 46.23,27.3 46.86,26.67 46.86,25.78 46.74,25.65 43.05,25.65 42.8,25.4 42.8,25.02
VDDS_DDR on BOTTOM: 18.47,8.48 19.13,8.48 19.28,8.33 19.28,7.57 19.48,7.37 20.07,7.37 20.73,6.71 21.92,6.71 22.15,6.93 22.15,7.26 22.3,7.42 23.55,7.42 23.72,7.24 23.72,6.12 23.29,5.69 19.15,5.69 18.31,6.53 18.31,8.33
VDDS_DDR on LYR3: 60.33,2.86 60.01,2.54 18.67,2.54 18.41,2.79 18.41,8.38 18.67,8.64 27.18,8.64 28.47,7.34 59.74,7.34 60.33,6.76
VDDS_DDR on LYR5_PWR: 49.4,30.35 49.4,25.27 49.66,25.02 50.04,25.02 50.29,24.77 50.29,20.7 49.4,19.81 49.4,5.84 49.85,5.4 60.33,5.4 60.64,5.71 60.64,15.88 60.96,16.19 66.62,16.19 68.47,18.03 68.48,18.03 68.48,29.97 64.16,34.29 50.67,34.29 50.42,34.04 50.42,31.37
P_L1 on TOP: 23.18,11.06 23.18,10.74 22.61,10.16 22.23,10.16 22.1,10.03 22.1,9.78 22.35,9.53 23.5,9.53 23.75,9.78 23.75,11.11 23.5,11.37
P_L1 on BOTTOM: 21.89,10.31 23.11,10.31 23.39,10.03 23.39,7.8 23.24,7.65 22.02,7.65 21.77,7.9 21.77,10.19
P_L2 on TOP: 24.64,9.53 24.38,9.78 24.38,10.67 24.51,10.79 24.51,11.46 24.64,11.59 24.73,11.59 25.53,10.79 25.53,9.78 25.27,9.53
P_L2 on BOTTOM: 24.05,10.36 25.32,10.36 25.48,10.21 25.48,8 25.12,7.65 23.98,7.65 23.75,7.87 23.75,10.06
P_L3 on TOP: 26.44,15.34 25.91,15.34 25.91,15.56 26.73,15.56 27.3,16.13 27.3,17.53 27.56,17.78 29.34,17.78 29.46,17.65 29.46,17.14 29.34,17.02 28.19,17.02 28.07,16.89 28.07,15.75 27.56,15.24 26.54,15.24
SYS_5V on TOP: 14.1,15.37 15.98,15.37 16.05,15.29 16.05,12.52 15.85,12.32 14,12.32 13.72,12.04 13.72,7.87 13.02,7.18 12.76,7.18 12.32,6.73 9.53,6.73 9.09,7.16 4.22,7.16 4.06,7.32 4.06,8.86 7.72,8.86 9.14,10.29 10.79,10.29 11.3,10.79 11.3,13.72 12.45,14.86 13.59,14.86
SYS_5V on BOTTOM: 4.14,9.55 5.08,9.55 5.18,9.45 5.18,7.32 5.03,7.16 4.22,7.16 4.06,7.32 4.06,9.47
SYS_5V on BOTTOM: 17.88,15.27 20.37,15.27 20.4,15.24 20.4,13.97 19.23,13.97 18.67,14.53 17.88,14.53 17.86,14.55 17.86,15.24
SYS_5V on LYR3: 25.02,19.56 26.42,18.16 26.42,17.78 27.43,16.76 27.43,15.24 24.77,12.57 24.77,10.92 24.64,10.79 23.88,10.79 23.11,11.56 21.72,11.56 18.67,14.61 18.41,14.61 17.48,13.67 17.07,13.67 16.21,12.8 12.85,12.8 12.52,13.13 12.52,13.92 12.93,14.33 15.47,14.33 17.02,15.88 17.02,17.14 17.78,17.91 21.46,17.91 22.48,18.92 22.48,19.05 22.99,19.56
USB1_PWR on BOTTOM: 6.02,15.32 6.35,14.99 6.35,14.2 6.73,13.82 8.08,13.82 8.56,13.34 8.56,12.57 8.05,12.06 6.32,12.06 5.89,12.5 4.14,12.5 4.04,12.6 4.04,15.27 4.09,15.32
USB_DC on TOP: 19.43,13.16 20.12,13.16 20.19,13.08 20.19,12.83 20.32,12.7 20.32,10.92 19.94,10.54 19.89,10.54 19.63,10.29 19.63,9.5 20.04,9.09 20.04,7.98 19.86,7.8 18.59,7.8 18.39,8 18.39,11.43 18.97,12.01 18.97,12.7
USB_DC on BOTTOM: 3.96,43.05 14.66,43.05 14.96,42.75 14.96,41.99 14.86,41.88 14.15,41.88 13.97,41.71 13.97,41.4 13.72,41.15 13.21,41.15 12.7,40.64 7.24,40.64 5.26,42.62 3.99,42.62 3.89,42.72 3.89,42.98
USB_DC on BOTTOM: 19.05,10.54 18.8,10.79 18.8,11.56 19.43,12.19 19.43,13.21 19.56,13.34 20.57,13.34 20.95,12.95 20.95,11.56 20.83,11.43 20.83,10.92 20.45,10.54
USB_DC on LYR4: 19.08,10.39 20.19,10.39 20.57,10.77 20.57,11.05 20.95,11.43 20.95,18.03 20.32,18.67 20.32,34.29 19.05,35.56 19.05,38.61 14.73,42.93 10.41,42.93 9.91,42.42 9.91,40.26 10.41,39.75 12.83,39.75 13.46,39.12 13.46,37.72 15.38,35.8 15.37,35.79 15.37,16.89 18.92,13.34 18.92,12.7 18.95,12.7 18.95,10.52
VDCDC1 on TOP: 20.51,10.73 22.23,10.73 22.96,11.47 22.96,12.19 23.16,12.19 23.16,11.29 22.99,11.11 22.99,10.79 22.48,10.29 21.84,10.29 21.59,10.03 21.59,9.78 21.34,9.53 20.07,9.53 19.81,9.78 19.81,10.16 20.32,10.67 20.45,10.67
VDCDC1 on BOTTOM: 21.21,10.01 21.21,7.92 20.98,7.7 19.94,7.7 19.76,7.87 19.76,8.41 19.35,8.81 18.59,8.81 18.41,8.99 18.41,9.75 18.95,10.29 20.93,10.29
VRTC on LYR3: 48.51,24.64 47.75,24.64 47.5,24.38 47.5,21.59 47.12,21.21 47.12,20.83 47.24,20.7 49.28,20.7 49.4,20.83 49.4,21.21 48.77,21.84 48.77,24.38
VRTC on LYR5_PWR: 47.37,20.32 49.53,20.32 50.04,20.83 50.04,24.64 49.91,24.77 47.24,24.77 47.12,24.64 47.12,20.57

Small or netless copper shapes (teardrops, artwork), in the pictures only: 253 on TOP, 137 on BOTTOM, 76 on LYR3, 19 on LYR4

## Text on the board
BOTTOM: LAYER 6 | SOLDER
Board Geometry/Soldermask Bottom: SMS
Ref Des/Silkscreen Bottom: microSD Card | USB | S/N | P4 | BSLK
TOP: BeagleBone_Green | C | v1.2 | LAYER 1 | COMPONENT
Board Geometry/Soldermask Top: SMC
Ref Des/Silkscreen Top: PWR | USER | RESET | POWER | AM335x | TXD | 3V3 | SDA | GND | RXD | SCL | USB Host | 10/100 Ethernet | (OZ) | LAYER 1 - PRIMARY SIDE - SIGNAL | LAYER 2 - GROUND PLANE | LAYER 3 - SIGNAL | LAYER 4 - SIGNAL | LAYER 5 - SPLIT POWER PLANE | LAYER 6 - SECONDARY SIDE - SIGNAL | LAYER# | COPPER WEIGHT | HALF+PLATING | IMPEDANCE CONTROL | +/- 10% | 50ohm SINGLE ENDED | TRACE WIDTH | TRACE WIDTH / SPACE | 90ohm DIFFERENTIAL | 100ohm DIFFERENTIAL | TSLK | 1 | 5.25 | 4.75 | 4.5/6.5 | 5.0/7.0 | 3.75/7.25 | 4.00/8.00 | LAYER STACK-UP - ALL DIMENSIONS IN INCHES
LYR2_GND: LAYER 2 | GROUND
LYR3: LAYER 3 | SIGNAL
LYR4: LAYER 4 | SIGNAL
LYR5_PWR: LAYER 5 | POWER
DIM_PLACEMENT: V_CUT
DISPLAY_TOP: SPC
DISPLAY_BOTTOM: SPS
DIMENSION: R.250 2X
USER_PART_NUM_TOP: TSLKC
USER_PART_NUM_BOTTOM: BSLKC
User.14: NONE
User.27: FIGURE | FINISHED_SIZE | 8.0 | 12.0 | 35.0 | 36.0 | 40.0 | 63.0 | 92.0 | 125.0 | 24.0 | 80.0 | 128.0 | DRILL CHART: TOP to BOTTOM | ALL UNITS ARE IN MILS | TOLERANCE_DRILL | +3.0/-3.0 | +0.0/-0.0 | +5.0/-5.0 | PLATED | NON-PLATED | QTY | 899 | 20 | 95 | 2 | 4 | 1056 | TOTAL HOLES:
User.29: FIGURE | FINISHED_SIZE | 42.0x20.0 | SLOT HOLES: TOP to BOTTOM | ALL UNITS ARE IN MILS | TOLERANCE_DRILL | +0.0/-0.0 | PLATED | QTY | 2 | TOTAL HOLES:
